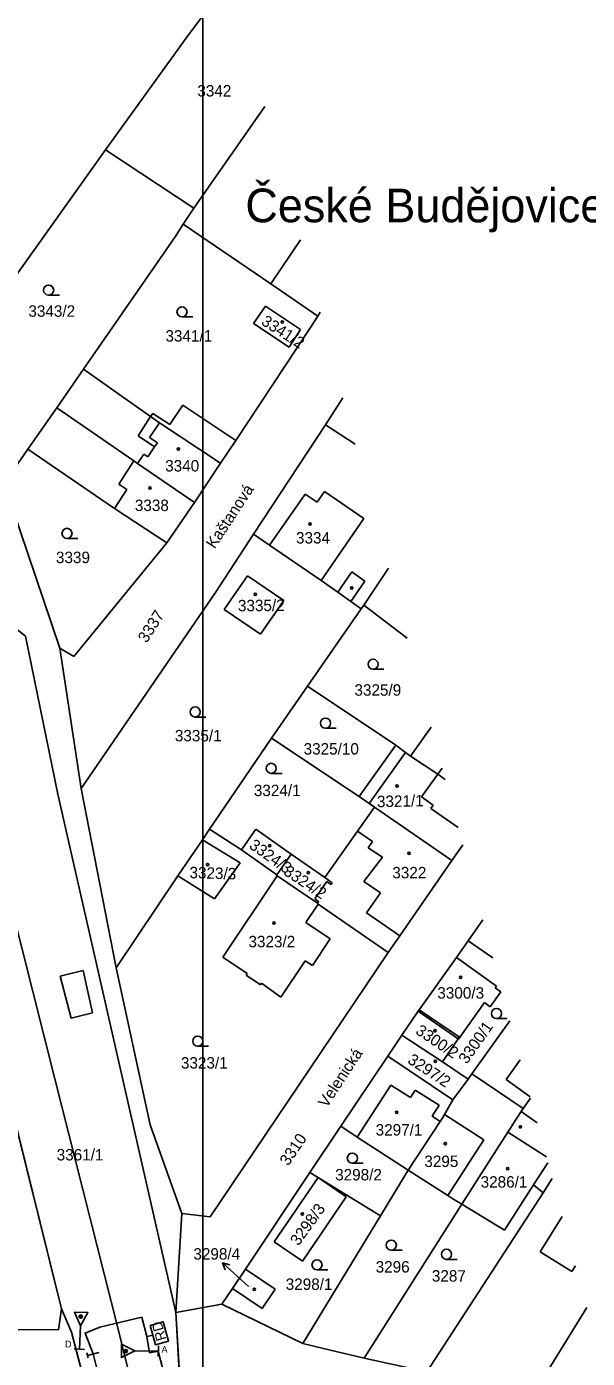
# Model space of a CAD drawing. Extents: x -754710 to -754206, y -1169123 to -1168234.
# Drawn here: x -754401.2 to -754317.9, y -1168952.2 to -1168754.2 of the extents above; entities that cross this region are included whole.
import ezdxf

# ---------------------------------------------------------------- set-up
doc = ezdxf.new("R2010")
doc.units = 0
for name, color, linetype in [('Vrstva 1', 7, 'Continuous'), ('Vrstva 15', 7, 'Continuous'), ('Vrstva 16', 7, 'Continuous'), ('Vrstva 18', 7, 'Continuous'), ('Vrstva 19', 7, 'Continuous'), ('Vrstva 23', 7, 'Continuous'), ('Vrstva 25', 7, 'Continuous'), ('Vrstva 3', 7, 'Continuous'), ('Vrstva 4', 7, 'Continuous'), ('Vrstva 45', 7, 'Continuous')]:
    doc.layers.add(name, color=color, linetype=linetype)

msp = doc.modelspace()

# ---------------------------------------------------------------- linework, layer by layer
at = {"layer": 'Vrstva 1'}
for p, q in [((-754372.58, -1168749.34), (-754377.16, -1168755.42)), ((-754377.16, -1168755.42), (-754389.49, -1168772.51)), ((-754365.79, -1168766.09), (-754376.38, -1168781.2)), ((-754389.49, -1168772.51), (-754413.83, -1168806.63)), ((-754389.49, -1168772.51), (-754376.38, -1168781.2)), ((-754376.38, -1168781.2), (-754377.93, -1168783.58)), ((-754377.93, -1168783.58), (-754379.13, -1168785.43)), ((-754377.93, -1168783.58), (-754364.93, -1168792.45)), ((-754392.76, -1168805.11), (-754379.13, -1168785.43)), ((-754364.93, -1168792.45), (-754360.49, -1168785.89)), ((-754364.93, -1168792.45), (-754357.94, -1168797.22)), ((-754367.47, -1168798.35), (-754365.73, -1168795.75)), ((-754365.73, -1168795.75), (-754360.48, -1168799.24)), ((-754357.94, -1168797.22), (-754359.12, -1168799.09)), ((-754357.6, -1168796.67), (-754357.94, -1168797.22)), ((-754359.12, -1168799.09), (-754370.14, -1168815.72)), ((-754362.21, -1168801.84), (-754367.47, -1168798.35)), ((-754360.48, -1168799.24), (-754362.21, -1168801.84)), ((-754396.75, -1168810.87), (-754392.76, -1168805.11)), ((-754382.78, -1168812.18), (-754392.76, -1168805.11)), ((-754354.19, -1168809.38), (-754356.8, -1168813.4)), ((-754401.03, -1168817.01), (-754396.75, -1168810.87)), ((-754385.26, -1168818.77), (-754396.75, -1168810.87)), ((-754382.78, -1168812.18), (-754381.45, -1168813.11)), ((-754372.41, -1168819.08), (-754381.45, -1168813.11)), ((-754367.49, -1168829.65), (-754356.8, -1168813.4)), ((-754356.8, -1168813.4), (-754352.35, -1168816.25)), ((-754370.14, -1168815.72), (-754372.41, -1168819.08)), ((-754404.58, -1168822.1), (-754401.03, -1168817.01)), ((-754401.03, -1168817.01), (-754388.18, -1168825.84)), ((-754384.72, -1168819.14), (-754385.26, -1168818.77)), ((-754376.28, -1168824.95), (-754384.72, -1168819.14)), ((-754372.41, -1168819.08), (-754376.28, -1168824.95)), ((-754396.3, -1168846.57), (-754404.58, -1168822.1)), ((-754380.38, -1168830.94), (-754388.18, -1168825.84)), ((-754376.28, -1168824.95), (-754380.38, -1168830.94)), ((-754373.15, -1168838.34), (-754367.49, -1168829.65)), ((-754367.49, -1168829.65), (-754365.1, -1168831.26)), ((-754380.38, -1168830.94), (-754394.21, -1168847.82)), ((-754357.41, -1168836.53), (-754365.1, -1168831.26)), ((-754371.84, -1168840.86), (-754368.4, -1168835.82)), ((-754368.4, -1168835.82), (-754362.97, -1168839.49)), ((-754347.4, -1168834.71), (-754351.09, -1168840.21)), ((-754354.97, -1168838.25), (-754357.41, -1168836.53)), ((-754393.12, -1168867.44), (-754373.15, -1168838.34)), ((-754362.97, -1168839.49), (-754366.43, -1168844.53)), ((-754353.01, -1168839.64), (-754354.97, -1168838.25)), ((-754351.46, -1168840.74), (-754353.01, -1168839.64)), ((-754366.43, -1168844.53), (-754371.84, -1168840.86)), ((-754359.46, -1168852.25), (-754351.46, -1168840.74)), ((-754351.09, -1168840.21), (-754351.46, -1168840.74)), ((-754351.09, -1168840.21), (-754344.62, -1168845.11)), ((-754401.41, -1168844.82), (-754396.56, -1168868.29)), ((-754394.21, -1168847.82), (-754396.3, -1168846.57)), ((-754396.3, -1168846.57), (-754393.12, -1168867.44)), ((-754359.46, -1168852.25), (-754364.83, -1168859.96)), ((-754346.33, -1168861), (-754359.46, -1168852.25)), ((-754341.07, -1168858.34), (-754344.14, -1168862.67)), ((-754364.83, -1168859.96), (-754374.01, -1168873.5)), ((-754364.83, -1168859.96), (-754351.77, -1168868.65)), ((-754346.33, -1168861), (-754344.87, -1168862.11)), ((-754350.27, -1168869.71), (-754344.87, -1168862.11)), ((-754344.87, -1168862.11), (-754344.14, -1168862.67)), ((-754344.14, -1168862.67), (-754340.1, -1168865.34)), ((-754340.1, -1168865.34), (-754338.99, -1168866.11)), ((-754393.12, -1168867.44), (-754387.93, -1168894.11)), ((-754396.56, -1168868.29), (-754379.05, -1168945.33)), ((-754351.77, -1168868.65), (-754350.27, -1168869.71)), ((-754349.52, -1168870.24), (-754352.02, -1168873.79)), ((-754350.27, -1168869.71), (-754349.52, -1168870.24)), ((-754349.52, -1168870.24), (-754338, -1168878.16)), ((-754378.72, -1168880.46), (-754375.09, -1168875.1)), ((-754374.01, -1168873.5), (-754375.09, -1168875.1)), ((-754375.09, -1168875.1), (-754369.49, -1168878.51)), ((-754374.01, -1168873.5), (-754369.28, -1168876.59)), ((-754369.28, -1168876.59), (-754367.16, -1168873.52)), ((-754367.16, -1168873.52), (-754361.87, -1168877.22)), ((-754356.89, -1168880.71), (-754352.02, -1168873.79)), ((-754364, -1168880.28), (-754369.28, -1168876.59)), ((-754361.87, -1168877.22), (-754364, -1168880.28)), ((-754361.87, -1168877.22), (-754356.89, -1168880.71)), ((-754338, -1168878.16), (-754336.49, -1168875.99)), ((-754336.38, -1168875.84), (-754336.49, -1168875.99)), ((-754369.49, -1168878.51), (-754373.29, -1168883.84)), ((-754338, -1168878.16), (-754345.75, -1168889.37)), ((-754387.93, -1168894.11), (-754378.72, -1168880.46)), ((-754373.29, -1168883.84), (-754378.72, -1168880.46)), ((-754372.07, -1168892.52), (-754363.97, -1168880.43)), ((-754363.97, -1168880.43), (-754364, -1168880.28)), ((-754357.95, -1168884.51), (-754363.97, -1168880.43)), ((-754356.58, -1168881.29), (-754358.39, -1168883.88)), ((-754356.89, -1168880.71), (-754355.81, -1168881.46)), ((-754355.99, -1168881.71), (-754356.58, -1168881.29)), ((-754355.81, -1168881.46), (-754355.99, -1168881.71)), ((-754357.88, -1168884.63), (-754359.73, -1168887.36)), ((-754358.39, -1168883.88), (-754357.79, -1168884.3)), ((-754357.79, -1168884.3), (-754357.95, -1168884.51)), ((-754357.88, -1168884.63), (-754357.95, -1168884.51)), ((-754347.46, -1168891.84), (-754357.88, -1168884.63)), ((-754335.56, -1168890.08), (-754333.4, -1168886.96)), ((-754359.73, -1168887.36), (-754356.08, -1168889.81)), ((-754356.08, -1168889.81), (-754358.74, -1168893.78)), ((-754345.75, -1168889.37), (-754347.46, -1168891.84)), ((-754335.56, -1168890.08), (-754337.33, -1168892.56)), ((-754331.89, -1168892.61), (-754335.56, -1168890.08)), ((-754347.46, -1168891.84), (-754373.92, -1168931.14)), ((-754368.43, -1168894.96), (-754372.07, -1168892.52)), ((-754359.8, -1168893.07), (-754363.42, -1168898.49)), ((-754358.74, -1168893.78), (-754359.8, -1168893.07)), ((-754337.33, -1168892.56), (-754342.88, -1168900.34)), ((-754337.33, -1168892.56), (-754331.34, -1168896.83)), ((-754382.87, -1168917.47), (-754387.93, -1168894.11)), ((-754368.59, -1168895.19), (-754368.43, -1168894.96)), ((-754366.44, -1168896.63), (-754368.59, -1168895.19)), ((-754366.29, -1168896.39), (-754366.44, -1168896.63)), ((-754363.42, -1168898.49), (-754366.29, -1168896.39)), ((-754331.34, -1168896.83), (-754331.56, -1168897.07)), ((-754331.56, -1168897.07), (-754330.71, -1168897.67)), ((-754330.71, -1168897.67), (-754332.28, -1168899.89)), ((-754343.03, -1168900.56), (-754345.45, -1168904.13)), ((-754342.88, -1168900.34), (-754343.03, -1168900.56)), ((-754336.88, -1168904.4), (-754342.88, -1168900.34)), ((-754333.13, -1168899.29), (-754337, -1168904.73)), ((-754332.28, -1168899.89), (-754333.13, -1168899.29)), ((-754406.43, -1168903.09), (-754396.05, -1168944.82)), ((-754335.01, -1168909.89), (-754329.38, -1168901.97)), ((-754347.54, -1168907.23), (-754345.45, -1168904.13)), ((-754345.45, -1168904.13), (-754339.41, -1168908.11)), ((-754337.07, -1168904.68), (-754339.41, -1168908.11)), ((-754336.88, -1168904.4), (-754337.07, -1168904.68)), ((-754337, -1168904.73), (-754337.07, -1168904.68)), ((-754354.49, -1168917.65), (-754347.54, -1168907.23)), ((-754347.54, -1168907.23), (-754337.87, -1168913.75)), ((-754339.41, -1168908.11), (-754335.55, -1168910.65)), ((-754329.94, -1168910.72), (-754327.83, -1168907.77)), ((-754335.55, -1168910.65), (-754337.87, -1168913.75)), ((-754335.55, -1168910.65), (-754335.01, -1168909.89)), ((-754327.41, -1168915.03), (-754335.01, -1168909.89)), ((-754326.35, -1168913.28), (-754329.94, -1168910.72)), ((-754337.87, -1168913.75), (-754339.09, -1168915.92)), ((-754327.41, -1168915.03), (-754327.69, -1168915.45)), ((-754327.41, -1168915.03), (-754326.3, -1168913.48)), ((-754339.72, -1168916.96), (-754344.47, -1168924.17)), ((-754339.34, -1168916.37), (-754339.72, -1168916.96)), ((-754339.09, -1168915.92), (-754339.34, -1168916.37)), ((-754327.69, -1168915.45), (-754328.88, -1168917.3)), ((-754327.69, -1168915.45), (-754325.31, -1168917.17)), ((-754378.13, -1168930.64), (-754382.87, -1168917.47)), ((-754359.09, -1168924.53), (-754354.49, -1168917.65)), ((-754352.09, -1168919.27), (-754354.49, -1168917.65)), ((-754329.66, -1168918.53), (-754332.16, -1168922.4)), ((-754329.28, -1168917.93), (-754329.66, -1168918.53)), ((-754329.66, -1168918.53), (-754323.95, -1168922.23)), ((-754328.88, -1168917.3), (-754329.28, -1168917.93)), ((-754344.47, -1168924.17), (-754352.09, -1168919.27)), ((-754332.16, -1168922.4), (-754336.53, -1168929.23)), ((-754368.68, -1168938.89), (-754359.09, -1168924.53)), ((-754359.09, -1168924.53), (-754348.61, -1168930.98)), ((-754344.47, -1168924.17), (-754348.61, -1168930.98)), ((-754338.58, -1168927.96), (-754344.47, -1168924.17)), ((-754323.71, -1168923.12), (-754325.86, -1168926.35)), ((-754364.41, -1168934.84), (-754357.89, -1168925.29)), ((-754357.89, -1168925.29), (-754353.69, -1168928.15)), ((-754330.19, -1168933.13), (-754325.86, -1168926.35)), ((-754325.86, -1168926.35), (-754324.43, -1168927.54)), ((-754324.43, -1168927.54), (-754323.09, -1168925.45)), ((-754353.69, -1168928.15), (-754360.19, -1168937.71)), ((-754341.72, -1168954.18), (-754324.43, -1168927.54)), ((-754337.83, -1168928.44), (-754338.58, -1168927.96)), ((-754336.53, -1168929.23), (-754337.83, -1168928.44)), ((-754379.05, -1168945.33), (-754378.13, -1168930.64)), ((-754373.92, -1168931.14), (-754378.13, -1168930.64)), ((-754351.06, -1168952.16), (-754336.53, -1168929.23)), ((-754336.53, -1168929.23), (-754330.19, -1168933.13)), ((-754348.61, -1168930.98), (-754360.17, -1168949.97)), ((-754324.89, -1168936.34), (-754321.59, -1168931.06)), ((-754360.19, -1168937.71), (-754364.41, -1168934.84)), ((-754320.17, -1168939.28), (-754324.89, -1168936.34)), ((-754319.62, -1168938.4), (-754320.17, -1168939.28)), ((-754370.59, -1168941.76), (-754368.68, -1168938.89)), ((-754368.68, -1168938.89), (-754364.27, -1168941.87)), ((-754372.18, -1168944.13), (-754370.59, -1168941.76)), ((-754366.21, -1168944.75), (-754370.59, -1168941.76)), ((-754364.27, -1168941.87), (-754366.21, -1168944.75)), ((-754379.05, -1168945.33), (-754372.18, -1168944.13)), ((-754372.18, -1168944.13), (-754360.17, -1168949.97)), ((-754326.09, -1168957.79), (-754317.95, -1168944.62)), ((-754396.5, -1168947.91), (-754396.05, -1168944.82)), ((-754396.05, -1168944.82), (-754394.57, -1168948.26)), ((-754379.05, -1168945.33), (-754378.16, -1168960.13)), ((-754418.54, -1168947.81), (-754396.5, -1168947.91)), ((-754394.57, -1168948.26), (-754386.06, -1168980.52)), ((-754360.17, -1168949.97), (-754357.06, -1168950.72)), ((-754391.33, -1168951.52), (-754389.35, -1168959.27)), ((-754381.64, -1168951.09), (-754379.68, -1168958.85)), ((-754357.06, -1168950.72), (-754351.06, -1168952.16)), ((-754351.06, -1168952.16), (-754341.72, -1168954.18))]:
    msp.add_line(p, q, dxfattribs=at)
for points in [[(-754378.16, -1168960.13), (-754379.05, -1168945.33), (-754396.56, -1168868.29), (-754401.41, -1168844.82), (-754410.22, -1168837.85), (-754411.61, -1168830.11), (-754417.05, -1168810.66), (-754423.83, -1168771.88), (-754425.2, -1168765.6), (-754426.48, -1168759.73), (-754431.15, -1168738.1), (-754436.63, -1168712.73), (-754441.87, -1168691.36), (-754448.68, -1168663.63), (-754450.74, -1168651.41), (-754451.5, -1168646.92), (-754451.93, -1168644.34), (-754452.67, -1168639.96), (-754460.6, -1168619.67)], [(-754451.95, -1168737.18), (-754445.36, -1168759.13), (-754439.11, -1168779.87), (-754435.88, -1168789.44), (-754434.68, -1168792.97), (-754429.46, -1168808.42), (-754424.9, -1168821.92), (-754424.54, -1168823.8), (-754420.6, -1168844.33), (-754415.45, -1168865.96), (-754412.65, -1168878.24), (-754410.06, -1168890.53), (-754406.43, -1168903.09), (-754396.05, -1168944.82), (-754394.57, -1168948.26), (-754386.06, -1168980.52)], [(-754367.04, -1169029.33), (-754371.5, -1169011.68), (-754383.94, -1168962.43), (-754384.99, -1168958.29), (-754386.56, -1168952.08), (-754387.62, -1168947.84), (-754397.03, -1168910.64), (-754410.17, -1168858.68)]]:
    msp.add_lwpolyline(points, dxfattribs=at)
at = {"layer": 'Vrstva 16'}
for p in [(-754372.08, -1168937.99), (-754368.24, -1168941.48)]:
    msp.add_line(p, (-754369.86, -1168940.01), dxfattribs=at)
msp.add_lwpolyline([(-754371.68, -1168939.03), (-754372.08, -1168937.99), (-754371, -1168938.29)], dxfattribs=at)
at = {"layer": 'Vrstva 23'}
msp.add_lwpolyline([(-754382.85, -1168947.26), (-754382.06, -1168950.14), (-754380.13, -1168949.6), (-754380.92, -1168946.72), (-754382.85, -1168947.26)], dxfattribs=at)
at = {"layer": 'Vrstva 25'}
for p, q in [((-754397.95, -1168794.11), (-754396.35, -1168794.11)), ((-754378.12, -1168797.36), (-754376.52, -1168797.36)), ((-754395.22, -1168830.28), (-754393.62, -1168830.28)), ((-754349.71, -1168849.74), (-754348.11, -1168849.74)), ((-754376.17, -1168856.83), (-754374.57, -1168856.83)), ((-754356.78, -1168858.49), (-754355.18, -1168858.49)), ((-754364.85, -1168865.21), (-754363.25, -1168865.21)), ((-754331.37, -1168901.65), (-754329.77, -1168901.65)), ((-754375.78, -1168905.77), (-754374.18, -1168905.77)), ((-754352.79, -1168923.16), (-754351.19, -1168923.16)), ((-754347, -1168936.09), (-754345.4, -1168936.09)), ((-754338.8, -1168937.45), (-754337.2, -1168937.45)), ((-754358.05, -1168939.02), (-754356.45, -1168939.02))]:
    msp.add_line(p, q, dxfattribs=at)
msp.add_lwpolyline([(-754327.72, -1168917.61), (-754327.63, -1168917.76), (-754327.72, -1168917.91), (-754327.9, -1168917.91), (-754327.99, -1168917.76), (-754327.9, -1168917.61)], close=True, dxfattribs=at)
for centre, radius in [((-754397.95, -1168793.36), 0.75), ((-754378.12, -1168796.61), 0.75), ((-754363.22, -1168798.13), 0.175), ((-754378.65, -1168817.01), 0.175), ((-754382.88, -1168822.78), 0.175), ((-754395.22, -1168829.53), 0.75), ((-754359.08, -1168828.13), 0.175), ((-754352.88, -1168837.67), 0.175), ((-754367.23, -1168838.59), 0.175), ((-754349.71, -1168848.99), 0.75), ((-754376.17, -1168856.08), 0.75), ((-754356.78, -1168857.74), 0.75), ((-754364.85, -1168864.46), 0.75), ((-754346.13, -1168867.08), 0.175), ((-754365.07, -1168875.96), 0.175), ((-754344.36, -1168877.08), 0.175), ((-754374.31, -1168878.76), 0.175), ((-754359.36, -1168879.95), 0.175), ((-754364.46, -1168887.44), 0.175), ((-754336.71, -1168895.52), 0.175), ((-754331.37, -1168900.9), 0.75), ((-754375.78, -1168905.02), 0.75), ((-754340.5, -1168903.48), 0.175), ((-754340.46, -1168908.03), 0.175), ((-754346.19, -1168915.58), 0.175), ((-754338.96, -1168920.25), 0.175), ((-754352.79, -1168922.41), 0.75), ((-754329.68, -1168923.96), 0.175), ((-754360.21, -1168930.73), 0.175), ((-754347, -1168935.34), 0.75), ((-754338.8, -1168936.7), 0.75), ((-754358.05, -1168938.27), 0.75), ((-754367.37, -1168941.89), 0.175)]:
    msp.add_circle(centre, radius, dxfattribs=at)
at = {"layer": 'Vrstva 3'}
msp.add_lwpolyline([(-754375, -1168707.79), (-754375, -1169000), (-754517.39, -1169000)], dxfattribs=at)
at = {"layer": 'Vrstva 4'}
for p, q in [((-754382.78, -1168812.18), (-754382.46, -1168811.69)), ((-754379.91, -1168813.36), (-754382.46, -1168811.69)), ((-754378.01, -1168810.48), (-754379.91, -1168813.36)), ((-754370.14, -1168815.72), (-754378.01, -1168810.48)), ((-754384.64, -1168815.03), (-754382.78, -1168812.18)), ((-754381.45, -1168813.11), (-754382.93, -1168815.28)), ((-754382.2, -1168816.65), (-754384.64, -1168815.03)), ((-754382.93, -1168815.28), (-754381.77, -1168816.07)), ((-754384.72, -1168819.14), (-754383.81, -1168817.76)), ((-754383.81, -1168817.76), (-754383.19, -1168818.16)), ((-754383.19, -1168818.16), (-754382.2, -1168816.65)), ((-754381.77, -1168816.07), (-754382.2, -1168816.65)), ((-754387.51, -1168822.22), (-754385.26, -1168818.77)), ((-754388.18, -1168825.84), (-754386.32, -1168823)), ((-754386.32, -1168823), (-754387.51, -1168822.22)), ((-754365.1, -1168831.26), (-754359.79, -1168823.7)), ((-754359.79, -1168823.7), (-754358.04, -1168824.91)), ((-754358.04, -1168824.91), (-754356.93, -1168823.29)), ((-754356.93, -1168823.29), (-754351.07, -1168827.32)), ((-754351.07, -1168827.32), (-754357.41, -1168836.53)), ((-754354.97, -1168838.25), (-754352.86, -1168835.27)), ((-754352.86, -1168835.27), (-754350.95, -1168836.62)), ((-754350.95, -1168836.62), (-754353.01, -1168839.64)), ((-754351.77, -1168868.65), (-754346.33, -1168861)), ((-754342.51, -1168868.7), (-754340.1, -1168865.34)), ((-754339.44, -1168864.42), (-754340.1, -1168865.34)), ((-754340.77, -1168869.92), (-754342.51, -1168868.7)), ((-754341.12, -1168870.43), (-754340.77, -1168869.92)), ((-754337.08, -1168873.25), (-754341.12, -1168870.43)), ((-754352.02, -1168873.79), (-754349.8, -1168875.35)), ((-754349.8, -1168875.35), (-754350.46, -1168876.3)), ((-754350.46, -1168876.3), (-754348.31, -1168877.68)), ((-754348.31, -1168877.68), (-754351.08, -1168881.29)), ((-754351.08, -1168881.29), (-754348.63, -1168882.99)), ((-754348.63, -1168882.99), (-754350.68, -1168885.96)), ((-754350.68, -1168885.96), (-754345.75, -1168889.37)), ((-754396.22, -1168895.33), (-754392.79, -1168894.53)), ((-754392.79, -1168894.53), (-754391.44, -1168900.79)), ((-754394.61, -1168901.6), (-754396.22, -1168895.33)), ((-754391.44, -1168900.79), (-754394.61, -1168901.6)), ((-754343.03, -1168900.56), (-754337.07, -1168904.68)), ((-754352.09, -1168919.27), (-754347.05, -1168911.55)), ((-754347.05, -1168911.55), (-754344.13, -1168913.38)), ((-754344.13, -1168913.38), (-754343.45, -1168912.29)), ((-754343.45, -1168912.29), (-754339.9, -1168914.51)), ((-754339.9, -1168914.51), (-754340.95, -1168916.19)), ((-754340.95, -1168916.19), (-754339.72, -1168916.96)), ((-754333.25, -1168919.67), (-754339.09, -1168915.92)), ((-754338.58, -1168927.96), (-754333.25, -1168919.67)), ((-754393.36, -1168946.13), (-754392.99, -1168945.8)), ((-754381.64, -1168951.87), (-754381.63, -1168950.31)), ((-754394.15, -1168950.76), (-754392.6, -1168950.84)), ((-754392.26, -1168951.35), (-754392.08, -1168952.1)), ((-754386.31, -1168951.27), (-754386.65, -1168950.91))]:
    msp.add_line(p, q, dxfattribs=at)
for points in [[(-754393.38, -1168950.8), (-754393.21, -1168947.33), (-754394.1, -1168945.28), (-754392.1, -1168945.37), (-754393.21, -1168947.33)], [(-754381.64, -1168951.09), (-754385.11, -1168951.07), (-754387.13, -1168952.04), (-754387.12, -1168950.04), (-754385.11, -1168951.07)], [(-754392.17, -1168951.72), (-754390.48, -1168951.31), (-754390.48, -1168951.31)]]:
    msp.add_lwpolyline(points, dxfattribs=at)
for centre in [(-754393.17, -1168945.97), (-754386.48, -1168951.09)]:
    msp.add_circle(centre, 0.248, dxfattribs=at)
at = {"layer": 'Vrstva 45'}
for points in [[(-754391.33, -1168951.52), (-754392.52, -1168948.41), (-754390.32, -1168947.54), (-754384.1, -1168946.05), (-754383.34, -1168948.91)], [(-754382.42, -1168948.71), (-754383.34, -1168948.91)], [(-754383.34, -1168948.91), (-754382.96, -1168951.34), (-754381.64, -1168951.09)]]:
    msp.add_lwpolyline(points, dxfattribs=at)

# ---------------------------------------------------------------- texts
at = {"layer": 'Vrstva 15'}
for s, p in [('Kaštanová', (-754373.26, -1168831.93)), ('Velenická', (-754356.59, -1168915.03))]:
    msp.add_text(s, height=1.7, rotation=56.7228, dxfattribs=at).set_placement(p)
at = {"layer": 'Vrstva 16'}
msp.add_text('3298/4', height=1.7, dxfattribs=at).set_placement((-754376.43, -1168937.49))
at = {"layer": 'Vrstva 18'}
for s, p in [('3342', (-754375.84, -1168764.59)), ('3343/2', (-754400.96, -1168797.33)), ('3341/1', (-754380.58, -1168801.02)), ('3339', (-754396.86, -1168833.95)), ('3325/9', (-754352.48, -1168853.66)), ('3335/1', (-754379.18, -1168860.45)), ('3325/10', (-754360.04, -1168862.41)), ('3324/1', (-754367.44, -1168868.59)), ('3323/1', (-754378.28, -1168909.09)), ('3361/1', (-754396.75, -1168922.75)), ('3298/2', (-754355.35, -1168925.72)), ('3296', (-754349.33, -1168939.41)), ('3298/1', (-754362.7, -1168941.99)), ('3287', (-754340.97, -1168940.76))]:
    msp.add_text(s, height=1.7, dxfattribs=at).set_placement(p)
for s, rotation, p in [('3337', 57.5823, (-754383.37, -1168845.92)), ('3300/1', 54.8894, (-754335.77, -1168908.53)), ('3310', 55.8061, (-754362.33, -1168923.66))]:
    msp.add_text(s, height=1.7, rotation=rotation, dxfattribs=at).set_placement(p)
at = {"layer": 'Vrstva 19'}
for s, rotation, p in [('3341/2', 327.3881, (-754366.47, -1168798.4)), ('3335/2', 0.5157, (-754369.8, -1168841.12)), ('3321/1', 1.0886, (-754349.12, -1168870.24)), ('3324/3', 324.9244, (-754368.26, -1168876.23)), ('3323/3', 358.3851, (-754377.03, -1168880.78)), ('3324/2', 326.6432, (-754363.16, -1168880.16)), ('3300/2', 326.2422, (-754343.52, -1168903.82)), ('3297/2', 326.7005, (-754344.71, -1168908.17)), ('3298/3', 53.9726, (-754360.81, -1168935.55))]:
    msp.add_text(s, height=1.7, rotation=rotation, dxfattribs=at).set_placement(p)
for s, height, p in [('3340', 1.7, (-754380.62, -1168820.33)), ('3338', 1.7, (-754385.13, -1168826.21)), ('3334', 1.7, (-754361.17, -1168831.04)), ('3322', 1.7, (-754346.85, -1168880.81)), ('3323/2', 1.7, (-754368.24, -1168891.06)), ('3300/3', 1.7, (-754340.16, -1168898.69)), ('3297/1', 1.7, (-754349.33, -1168919.05)), ('3295', 1.7, (-754342.09, -1168923.72)), ('3286/1', 1.7, (-754333.72, -1168926.79)), ('3298/4', 0.1, (-754368.23, -1168941.48))]:
    msp.add_text(s, height=height, dxfattribs=at).set_placement(p)
at = {"layer": 'Vrstva 23'}
msp.add_text('RD', height=1.5, rotation=105.7615, dxfattribs=at).set_placement((-754380.43, -1168949.32))
at = {"layer": 'Vrstva 3'}
msp.add_text('České Budějovice 1-4/14', height=5, dxfattribs=at).set_placement((-754368.7, -1168783.28))
at = {"layer": 'Vrstva 4'}
for s, p in [('D', (-754395.51, -1168950.55)), ('A', (-754381.16, -1168951.33))]:
    msp.add_text(s, height=1, dxfattribs=at).set_placement(p)

doc.saveas('drawing.dxf')
